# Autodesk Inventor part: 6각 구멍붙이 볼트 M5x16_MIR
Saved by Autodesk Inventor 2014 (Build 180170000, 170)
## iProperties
Created: 2026-10
Part Number: 6각 구멍붙이 볼트 M5x16_MIR
Material: 일반
Document SubType Name: Modeling
Designer: dg
Density: 1 g/cm^3
Appearance: 기본값
Author: dg
Author: jhkim
Description: 6각머리 태핑 나사
Creation Date: 2026-09-29
Sending System: Autodesk Inventor 2027
Preprocessor: ST-DEVELOPER v20.1
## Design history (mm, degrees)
derived "6각 구멍붙이 볼트 M5x16.ipt"
feature "Solid1::6각 구멍붙이 볼트 M5x16.ipt" dims "d0" = 10
tag "피쳐 태그1"
node "솔리드1"
